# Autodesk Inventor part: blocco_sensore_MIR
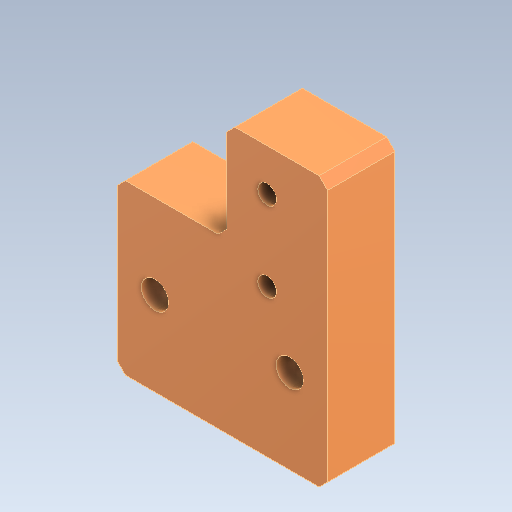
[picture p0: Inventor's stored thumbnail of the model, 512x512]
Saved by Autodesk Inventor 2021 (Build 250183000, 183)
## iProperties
Created: 2026-01
Part Number: blocco_sensore_MIR
Material: Plastica ABS
Document SubType Name: Modeling
Designer: hp
Density: 1.06 g/cm^3
Appearance: Default
Author: hp
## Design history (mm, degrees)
feature "Solido1"
body "Solid1"
